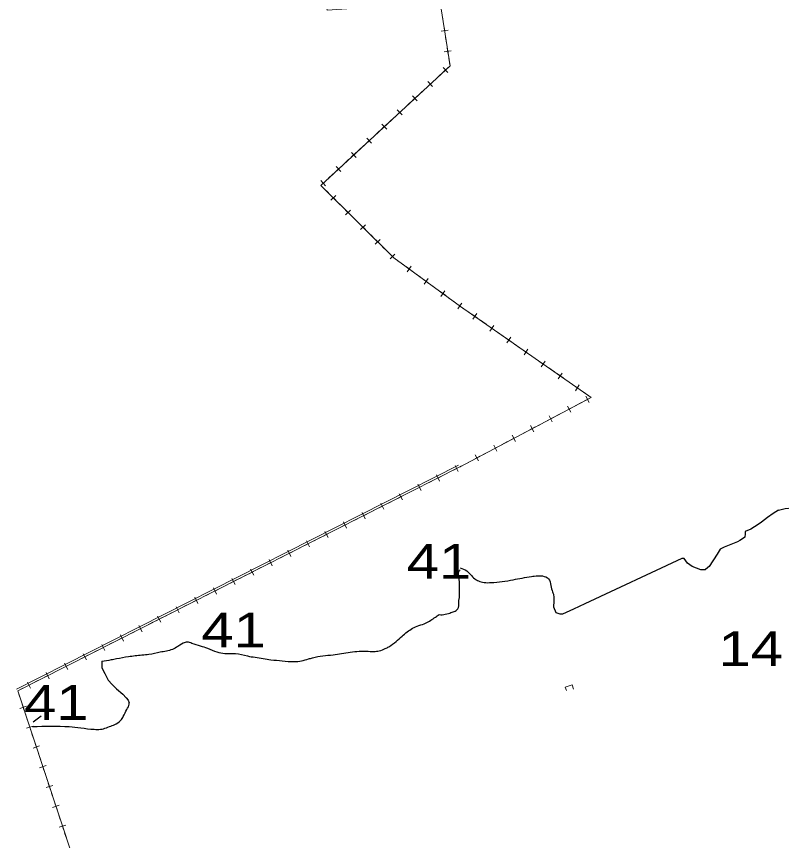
# Model space of a CAD drawing. Extents: x 476989 to 498418, y 4381813 to 4416555.
# Drawn here: x 483464 to 484565, y 4384627 to 4385812 of the extents above; entities that cross this region are included whole.
import ezdxf
from ezdxf.enums import TextEntityAlignment as Align

# ---------------------------------------------------------------- set-up
doc = ezdxf.new("R2010")
doc.units = 0
doc.header["$LTSCALE"] = 20
doc.linetypes.add('MEDIUM_DASHED', pattern=[4.5, 3, -1.5])
for name, color, linetype, lineweight in [('13', 7, 'Continuous', 13), ('34', 7, 'Continuous', 13), ('48', 7, 'MEDIUM_DASHED', 13), ('6', 7, 'Continuous', 25)]:
    doc.layers.add(name, color=color, linetype=linetype, lineweight=lineweight)

msp = doc.modelspace()

# ---------------------------------------------------------------- linework, layer by layer
at = {"layer": '34'}
for p, q in [((484077.16, 4385811.45), (484078.68, 4385801.57)), ((484075.26, 4385790.93), (484085.14, 4385792.45)), ((484079.44, 4385796.63), (484080.96, 4385786.74)), ((484081.72, 4385781.8), (484083.24, 4385771.92)), ((484084, 4385766.98), (484085.52, 4385757.09)), ((484079.82, 4385761.27), (484089.71, 4385762.79)), ((484086.28, 4385752.15), (484087.81, 4385742.27)), ((484085.27, 4385738.48), (484077.93, 4385731.69)), ((484078.2, 4385738.75), (484084.99, 4385731.41)), ((484063.24, 4385718.11), (484055.9, 4385711.32)), ((484056.18, 4385718.38), (484062.97, 4385711.04)), ((484074.26, 4385728.29), (484066.92, 4385721.5)), ((484052.23, 4385707.92), (484044.89, 4385701.13)), ((484041.22, 4385697.74), (484033.88, 4385690.95)), ((484034.15, 4385698.02), (484040.94, 4385690.67)), ((484030.21, 4385687.56), (484022.86, 4385680.77)), ((484019.19, 4385677.37), (484011.85, 4385670.58)), ((484012.13, 4385677.65), (484018.92, 4385670.31)), ((484008.18, 4385667.19), (484000.84, 4385660.4)), ((483986.15, 4385646.82), (483978.81, 4385640.03)), ((483997.17, 4385657), (483989.82, 4385650.21)), ((483990.1, 4385657.28), (483996.89, 4385649.94)), ((483975.14, 4385636.64), (483967.8, 4385629.85)), ((483968.07, 4385636.91), (483974.86, 4385629.57)), ((483964.13, 4385626.45), (483956.79, 4385619.66)), ((483953.11, 4385616.27), (483945.77, 4385609.48)), ((483946.05, 4385616.54), (483952.84, 4385609.2)), ((483942.1, 4385606.08), (483934.76, 4385599.29)), ((483931.09, 4385595.9), (483923.75, 4385589.11)), ((483924.02, 4385596.18), (483930.81, 4385588.83)), ((483902, 4385575.81), (483908.79, 4385568.47)), ((483920.08, 4385585.71), (483912.73, 4385578.93)), ((483905.82, 4385565.21), (483912.93, 4385558.18)), ((483916.48, 4385554.66), (483923.58, 4385547.62)), ((483916.51, 4385547.59), (483923.55, 4385554.69)), ((483927.14, 4385544.1), (483934.24, 4385537.06)), ((483937.79, 4385533.55), (483944.9, 4385526.51)), ((483937.83, 4385526.48), (483944.87, 4385533.58)), ((483948.45, 4385522.99), (483955.56, 4385515.95)), ((483959.11, 4385512.43), (483966.21, 4385505.4)), ((483959.14, 4385505.36), (483966.18, 4385512.47)), ((483969.77, 4385501.88), (483976.87, 4385494.84)), ((483980.42, 4385491.32), (483987.53, 4385484.29)), ((483980.46, 4385484.25), (483987.49, 4385491.36)), ((483991.08, 4385480.77), (483998.19, 4385473.73)), ((484001.77, 4385463.14), (484008.81, 4385470.25)), ((484013.14, 4385460.53), (484021.22, 4385454.63)), ((484025.26, 4385451.69), (484033.34, 4385445.8)), ((484026.35, 4385444.7), (484032.24, 4385452.78)), ((484037.38, 4385442.85), (484045.46, 4385436.96)), ((484049.5, 4385434.01), (484057.58, 4385428.12)), ((484050.59, 4385427.03), (484056.48, 4385435.11)), ((484061.62, 4385425.18), (484069.7, 4385419.28)), ((484073.74, 4385416.34), (484081.82, 4385410.45)), ((484074.83, 4385409.35), (484080.72, 4385417.43)), ((484085.86, 4385407.5), (484093.94, 4385401.61)), ((484097.98, 4385398.66), (484103, 4385395)), ((484103.23, 4385397.38), (484104.96, 4385399.76)), ((484099.07, 4385391.68), (484103.23, 4385397.38)), ((484107.1, 4385392.14), (484115.31, 4385386.42)), ((484119.41, 4385383.57), (484127.61, 4385377.85)), ((484120.65, 4385376.61), (484126.37, 4385384.81)), ((484131.72, 4385374.99), (484139.92, 4385369.27)), ((484144.02, 4385366.41), (484152.23, 4385360.7)), ((484145.27, 4385359.45), (484150.98, 4385367.66)), ((484156.33, 4385357.84), (484164.53, 4385352.12)), ((484169.88, 4385342.3), (484175.6, 4385350.51)), ((484168.64, 4385349.26), (484176.84, 4385343.55)), ((484180.94, 4385340.69), (484189.15, 4385334.97)), ((484193.25, 4385332.11), (484201.46, 4385326.4)), ((484194.49, 4385325.15), (484200.21, 4385333.36)), ((484205.56, 4385323.54), (484213.76, 4385317.82)), ((484217.86, 4385314.96), (484226.07, 4385309.24)), ((484219.11, 4385308), (484224.83, 4385316.21)), ((484230.17, 4385306.39), (484238.38, 4385300.67)), ((484242.48, 4385297.81), (484250.68, 4385292.09)), ((484243.72, 4385290.85), (484249.44, 4385299.05)), ((484254.79, 4385289.23), (484262.99, 4385283.52)), ((484267.09, 4385280.66), (484275.3, 4385274.94)), ((484268.34, 4385273.7), (484274.05, 4385281.9)), ((484279.4, 4385272.08), (484287.6, 4385266.37)), ((484276.98, 4385256.58), (484268.14, 4385251.91)), ((484290.24, 4385263.6), (484281.4, 4385258.92)), ((484283.48, 4385265.68), (484288.16, 4385256.84)), ((484263.72, 4385249.57), (484254.88, 4385244.89)), ((484256.96, 4385251.65), (484261.64, 4385242.81)), ((484237.21, 4385235.54), (484228.37, 4385230.86)), ((484230.45, 4385237.62), (484235.12, 4385228.78)), ((484250.46, 4385242.55), (484241.62, 4385237.88)), ((484210.69, 4385221.51), (484201.85, 4385216.83)), ((484203.93, 4385223.59), (484208.61, 4385214.75)), ((484223.95, 4385228.52), (484215.11, 4385223.85)), ((484177.41, 4385209.56), (484182.09, 4385200.72)), ((484197.43, 4385214.49), (484188.59, 4385209.82)), ((484170.91, 4385200.46), (484162.07, 4385195.79)), ((484184.17, 4385207.48), (484175.33, 4385202.8)), ((484144.4, 4385186.43), (484135.56, 4385181.75)), ((484157.65, 4385193.45), (484148.82, 4385188.77)), ((484150.9, 4385195.53), (484155.57, 4385186.69)), ((484131.14, 4385179.42), (484122.3, 4385174.74)), ((484124.38, 4385181.5), (484129.06, 4385172.66)), ((484100.12, 4385166.55), (483464.12, 4384844.55)), ((484100.12, 4385166.55), (483464.12, 4384844.55)), ((484102, 4385164), (483466, 4384842)), ((484102, 4385164), (484093.09, 4385159.49)), ((484099.81, 4385157.29), (484095.29, 4385166.21)), ((484102.72, 4385164.38), (484102, 4385164)), ((484102.72, 4385164.38), (484102, 4385164)), ((484104.62, 4385165.39), (484102.72, 4385164.38)), ((484117.88, 4385172.4), (484109.04, 4385167.72)), ((484075.25, 4385150.46), (484066.33, 4385145.94)), ((484073.05, 4385143.74), (484068.53, 4385152.66)), ((484088.63, 4385157.23), (484079.7, 4385152.71)), ((484048.5, 4385136.91), (484039.57, 4385132.39)), ((484046.29, 4385130.19), (484041.78, 4385139.11)), ((484061.87, 4385143.68), (484052.95, 4385139.17)), ((484019.54, 4385116.65), (484015.02, 4385125.57)), ((484035.11, 4385130.14), (484026.19, 4385125.62)), ((484008.36, 4385116.59), (483999.44, 4385112.07)), ((484021.74, 4385123.37), (484012.82, 4385118.85)), ((483981.6, 4385103.04), (483972.68, 4385098.53)), ((483994.98, 4385109.82), (483986.06, 4385105.3)), ((483992.78, 4385103.1), (483988.26, 4385112.02)), ((483954.85, 4385089.5), (483945.92, 4385084.98)), ((483968.23, 4385096.27), (483959.31, 4385091.76)), ((483966.03, 4385089.55), (483961.51, 4385098.47)), ((483941.47, 4385082.73), (483932.55, 4385078.21)), ((483939.27, 4385076.01), (483934.75, 4385084.93)), ((483914.72, 4385069.18), (483905.79, 4385064.66)), ((483912.51, 4385062.46), (483908, 4385071.38)), ((483928.09, 4385075.95), (483919.17, 4385071.43)), ((483887.96, 4385055.63), (483879.04, 4385051.12)), ((483885.76, 4385048.91), (483881.24, 4385057.84)), ((483901.33, 4385062.4), (483892.41, 4385057.89)), ((483861.2, 4385042.09), (483852.28, 4385037.57)), ((483859, 4385035.37), (483854.48, 4385044.29)), ((483874.58, 4385048.86), (483865.65, 4385044.34)), ((483832.24, 4385021.82), (483827.73, 4385030.74)), ((483847.82, 4385035.31), (483838.9, 4385030.79)), ((483821.06, 4385021.77), (483812.14, 4385017.25)), ((483834.45, 4385028.54), (483825.52, 4385024.02)), ((483794.31, 4385008.22), (483785.39, 4385003.7)), ((483807.69, 4385014.99), (483798.77, 4385010.48)), ((483805.49, 4385008.27), (483800.97, 4385017.2)), ((483767.55, 4384994.67), (483758.63, 4384990.16)), ((483780.93, 4385001.45), (483772.01, 4384996.93)), ((483778.73, 4384994.73), (483774.21, 4385003.65)), ((483754.18, 4384987.9), (483745.26, 4384983.38)), ((483751.98, 4384981.18), (483747.46, 4384990.1)), ((483727.42, 4384974.36), (483718.5, 4384969.84)), ((483725.22, 4384967.64), (483720.7, 4384976.56)), ((483740.8, 4384981.13), (483731.87, 4384976.61)), ((483700.67, 4384960.81), (483691.74, 4384956.29)), ((483698.46, 4384954.09), (483693.95, 4384963.01)), ((483714.04, 4384967.58), (483705.12, 4384963.06)), ((483673.91, 4384947.26), (483664.99, 4384942.75)), ((483671.71, 4384940.54), (483667.19, 4384949.46)), ((483687.28, 4384954.03), (483678.36, 4384949.52)), ((483644.95, 4384927), (483640.43, 4384935.92)), ((483660.53, 4384940.49), (483651.61, 4384935.97)), ((483633.77, 4384926.94), (483624.85, 4384922.42)), ((483647.15, 4384933.72), (483638.23, 4384929.2)), ((483607.01, 4384913.39), (483598.09, 4384908.88)), ((483620.4, 4384920.17), (483611.48, 4384915.65)), ((483618.19, 4384913.45), (483613.68, 4384922.37)), ((483580.26, 4384899.85), (483571.34, 4384895.33)), ((483593.64, 4384906.62), (483584.72, 4384902.11)), ((483591.44, 4384899.9), (483586.92, 4384908.83)), ((483566.88, 4384893.08), (483557.96, 4384888.56)), ((483564.68, 4384886.36), (483560.17, 4384895.28)), ((483540.13, 4384879.53), (483531.21, 4384875.01)), ((483537.93, 4384872.81), (483533.41, 4384881.73)), ((483553.5, 4384886.3), (483544.58, 4384881.78)), ((483513.37, 4384865.98), (483504.45, 4384861.47)), ((483511.17, 4384859.26), (483506.65, 4384868.19)), ((483526.75, 4384872.75), (483517.82, 4384868.24)), ((483486.62, 4384852.44), (483477.69, 4384847.92)), ((483484.41, 4384845.72), (483479.9, 4384854.64)), ((483499.99, 4384859.21), (483491.07, 4384854.69)), ((483473.23, 4384845.66), (483466, 4384842)), ((483466, 4384842), (483699.09, 4384136.76)), ((483467.57, 4384837.25), (483470.71, 4384827.76)), ((483469.1, 4384816.69), (483478.59, 4384819.83)), ((483472.28, 4384823.01), (483475.41, 4384813.52)), ((483476.98, 4384808.77), (483480.12, 4384799.27)), ((483481.69, 4384794.53), (483484.83, 4384785.03)), ((483478.51, 4384788.21), (483488.01, 4384791.35)), ((483486.4, 4384780.28), (483489.54, 4384770.79)), ((483487.93, 4384759.72), (483497.42, 4384762.86)), ((483491.11, 4384766.04), (483494.24, 4384756.55)), ((483495.81, 4384751.8), (483498.95, 4384742.3)), ((483497.34, 4384731.24), (483506.84, 4384734.38)), ((483500.52, 4384737.56), (483503.66, 4384728.06)), ((483505.23, 4384723.31), (483508.37, 4384713.82)), ((483506.76, 4384702.76), (483516.25, 4384705.89)), ((483509.94, 4384709.07), (483513.07, 4384699.58)), ((483514.64, 4384694.83), (483517.78, 4384685.34)), ((483516.17, 4384674.27), (483525.67, 4384677.41)), ((483519.35, 4384680.59), (483522.49, 4384671.09)), ((483524.06, 4384666.35), (483527.2, 4384656.85)), ((483528.76, 4384652.1), (483531.9, 4384642.61)), ((483525.59, 4384645.79), (483535.08, 4384648.93)), ((483533.47, 4384637.86), (483536.61, 4384628.37))]:
    msp.add_line(p, q, dxfattribs=at)
for points in [[(483872.5, 4386448.65), (483868, 4386266), (483874, 4385990), (483911, 4385821), (484074, 4385832), (484088, 4385741), (483902, 4385569), (484007, 4385465), (484103, 4385395), (484103.22, 4385394.84)], [(483909.06, 4385575.53), (483902, 4385569), (483902.27, 4385568.73)], [(484001.74, 4385470.21), (484007, 4385465), (484009.1, 4385463.47)], [(484103.22, 4385394.84), (484291, 4385264), (484102.72, 4385164.38)]]:
    msp.add_lwpolyline(points, dxfattribs=at)
at = {"layer": '48'}
msp.add_lwpolyline([(484265.71, 4384844.4), (484263.66, 4384850.43), (484253.69, 4384847.41), (484255.71, 4384842.64)], dxfattribs=at)
at = {"layer": '6'}
msp.add_line((483487.94, 4384797.22), (483499.52, 4384805.78), dxfattribs=at)
for points in [[(484560.92, 4385101.66), (484570.5, 4385104.22), (484580.6, 4385105.21), (484596.61, 4385106.51), (484618.44, 4385108.14), (484667.62, 4385110.91), (484693.66, 4385111.99), (484721.33, 4385113.65)], [(484560.92, 4385101.66), (484552.79, 4385097.07), (484544.91, 4385091.31), (484536.45, 4385084.76), (484531.54, 4385081.19), (484520.76, 4385074.46), (484512.97, 4385071.07)], [(484512.97, 4385071.07), (484512.88, 4385067.92), (484512.1, 4385063.1), (484510.53, 4385061.38), (484505.04, 4385058.19), (484501.9, 4385056.36), (484482.31, 4385048.73), (484476.84, 4385045.76), (484472.32, 4385038.32), (484460.76, 4385021.04), (484459.08, 4385019.18)], [(484459.08, 4385019.18), (484455.39, 4385016.01), (484448.82, 4385016.01), (484436.64, 4385020.7), (484429.76, 4385025.69), (484424.76, 4385032.25), (484421.64, 4385032.25), (484282.12, 4384967.05), (484265.88, 4384959.56), (484249.94, 4384952.38), (484246.29, 4384952.07), (484240.98, 4384954.25), (484237.23, 4384962.37)], [(483587.08, 4384884.42), (483587.05, 4384881.67), (483587.05, 4384875.1), (483591.44, 4384866.7), (483596.19, 4384857.2), (483602.04, 4384850.99), (483608.25, 4384844.79), (483617.02, 4384837.12), (483622.14, 4384832), (483624.7, 4384828.35), (483626.16, 4384824.7)]]:
    msp.add_lwpolyline(points, dxfattribs=at)
for points in [[(484102.41, 4385018.95), (484112.24, 4385014.43), (484123.49, 4385003.19), (484128.93, 4385000.06), (484136.94, 4384997.86), (484147.17, 4384997.68), (484163.2, 4384999.01), (484178.72, 4385001.76), (484191.97, 4385004.19), (484205.12, 4385006.55), (484209.27, 4385007.05), (484220.87, 4385007.19), (484229.91, 4385002.93), (484233.01, 4384993.54), (484235.57, 4384984.24), (484237.09, 4384979.61), (484237.41, 4384971.23), (484237.15, 4384965.97), (484236.81, 4384962.99)], [(484072.71, 4384951.59), (484076.5, 4384951.46), (484085.91, 4384953.29), (484092.76, 4384955.65), (484097.86, 4384958.35), (484100.69, 4384966.27), (484100.68, 4384971.57), (484101.12, 4384973.91), (484101.59, 4384983.01), (484101.76, 4384992.72), (484101.64, 4384996.31), (484100.61, 4385007.16), (484100.17, 4385012.34), (484102.4, 4385016.18)], [(483716.09, 4384910.37), (483728.56, 4384906.5), (483738.81, 4384903.36), (483752.37, 4384897.87), (483764.13, 4384895.72), (483779.16, 4384895.71), (483796.36, 4384892.11), (483807.84, 4384890.22), (483830.33, 4384886.7), (483846.47, 4384885.23), (483863.98, 4384883.97), (483884.43, 4384887.78), (483890.35, 4384889.54), (483919.76, 4384893.88), (483931.93, 4384895.43), (483957.16, 4384898.9), (483978.14, 4384898.71), (483986.19, 4384899.52), (483994.88, 4384902.79), (484000, 4384905.38), (484010.44, 4384913.01), (484018.97, 4384920.5), (484033.93, 4384931.86), (484052.96, 4384939.49), (484067.04, 4384947.89), (484072.38, 4384951.59)], [(483716.44, 4384910.09), (483713.2, 4384911.45), (483706.93, 4384911.47), (483696.46, 4384905.89), (483688.57, 4384901.53), (483670.94, 4384897.44), (483654.77, 4384894.2), (483644.64, 4384893.16), (483625.55, 4384890.89), (483607.97, 4384887.86), (483600.49, 4384886.38), (483586.8, 4384884.38)], [(483487.33, 4384790.49), (483540.08, 4384790.42), (483556.51, 4384788.6), (483575.76, 4384786.62), (483585.08, 4384786.62), (483601.9, 4384792.09), (483605.46, 4384793.49), (483613.98, 4384799.33), (483617.78, 4384805.09), (483622.97, 4384815.2), (483626.22, 4384822.95), (483626.1, 4384824.59)]]:
    msp.add_spline(points, degree=3, dxfattribs=at)

# ---------------------------------------------------------------- texts
at = {"layer": '13', "width": 1.25}
for s, p in [('41', (484072.15, 4385003.14)), ('41', (483776.57, 4384904.3)), ('14', (484520.76, 4384877.59)), ('41', (483521.45, 4384800.16))]:
    msp.add_text(s, height=50, dxfattribs=at).set_placement(p, align=Align.CENTER)

doc.saveas('drawing.dxf')
